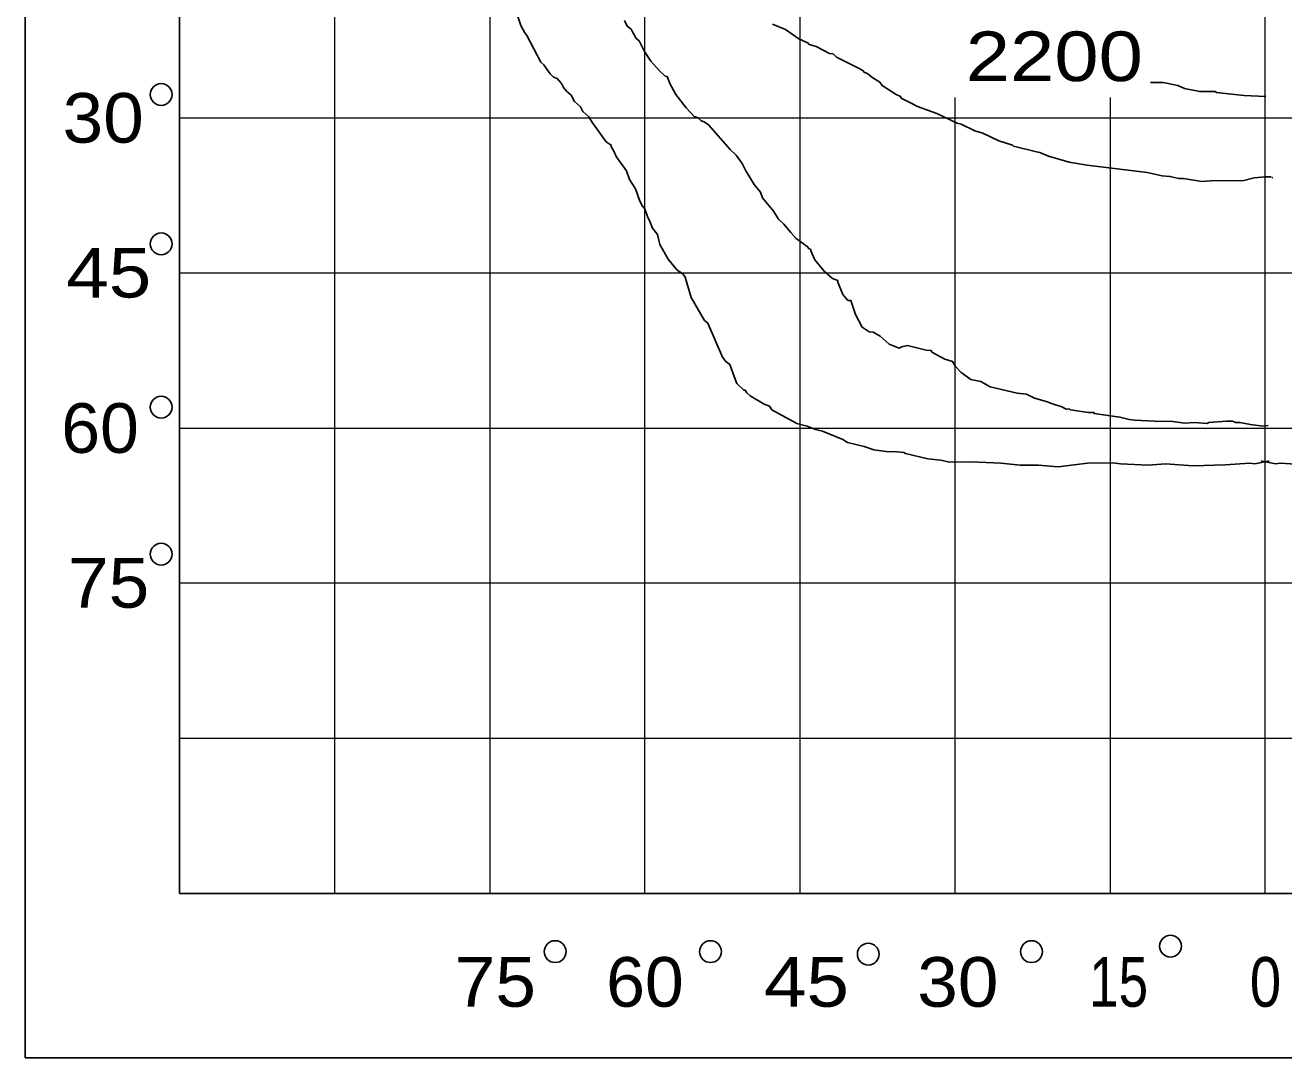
# Model space of a CAD drawing. Extents: x -39.6 to 16.1, y -17.6 to 34.
# Drawn here: x 8.955 to 11.491, y 19.458 to 21.539 of the extents above; entities that cross this region are included whole.
import ezdxf
from ezdxf.enums import TextEntityAlignment as Align

# ---------------------------------------------------------------- set-up
doc = ezdxf.new("R2010")
doc.units = 0
doc.header["$LTSCALE"] = 0.05
doc.layers.add('1', color=7, linetype='Continuous', lineweight=13)

msp = doc.modelspace()

# ---------------------------------------------------------------- linework, layer by layer
at = {"layer": '1', "lineweight": 25}
for p, q in [((8.95479, 19.45842), (8.95479, 24.24542)), ((9.26579, 19.78942), (9.26579, 23.85242)), ((11.46879, 21.23242), (11.46679, 21.23142)), ((9.26579, 19.78942), (13.95379, 19.78942)), ((8.95479, 19.45842), (13.95379, 19.45842))]:
    msp.add_line(p, q, dxfattribs=at)
at = {"layer": '1'}
for p, q in [((9.57879, 19.78942), (9.57879, 23.85242)), ((9.89179, 19.78942), (9.89179, 23.85242)), ((10.20379, 19.78942), (10.20379, 23.85242)), ((10.51679, 19.78942), (10.51679, 23.85242)), ((11.45379, 19.78942), (11.45379, 23.85242)), ((10.82879, 19.78942), (10.82879, 21.39342)), ((11.14179, 19.78942), (11.14179, 21.39342)), ((9.26579, 21.35242), (13.40679, 21.35242)), ((9.26579, 21.04042), (13.41179, 21.04042)), ((9.26579, 20.72742), (13.42279, 20.72742)), ((9.26579, 20.41542), (13.95379, 20.41542)), ((9.26579, 20.10242), (13.95379, 20.10242))]:
    msp.add_line(p, q, dxfattribs=at)
at = {"layer": '1', "lineweight": 25}
for points in [[(9.94279, 21.57042), (9.95379, 21.53842), (9.96179, 21.52342), (9.96579, 21.51842), (9.99379, 21.46442), (9.99979, 21.45942), (10.01279, 21.44142), (10.01979, 21.43442), (10.02679, 21.43142), (10.03579, 21.42142), (10.03979, 21.41342), (10.04579, 21.40642), (10.05479, 21.39842), (10.06179, 21.38542), (10.07379, 21.37442), (10.07879, 21.36542), (10.09079, 21.35442), (10.09779, 21.34242), (10.12579, 21.30442), (10.13579, 21.29742), (10.13579, 21.29442), (10.14079, 21.28542), (10.14579, 21.27442), (10.16679, 21.24542), (10.17279, 21.22842), (10.18479, 21.20942), (10.19379, 21.18442), (10.19879, 21.17442), (10.20379, 21.16942), (10.20879, 21.15342), (10.21379, 21.14342), (10.21879, 21.13042), (10.22879, 21.11742), (10.23379, 21.09742), (10.25079, 21.06742), (10.26879, 21.04542), (10.27979, 21.03842), (10.28479, 21.03142), (10.29679, 20.99042), (10.32379, 20.94442), (10.33079, 20.93842), (10.35979, 20.87042), (10.36679, 20.86142), (10.37479, 20.85542), (10.38179, 20.83642), (10.38879, 20.81742), (10.40279, 20.80342), (10.40579, 20.80342), (10.40879, 20.79842), (10.41579, 20.79242), (10.44379, 20.77542), (10.45479, 20.77142), (10.45979, 20.76442), (10.50979, 20.73642), (10.53079, 20.73142), (10.54779, 20.72442), (10.56179, 20.72142), (10.60279, 20.70442), (10.61179, 20.69842), (10.64579, 20.69042), (10.66479, 20.68342), (10.69479, 20.67942), (10.70279, 20.68042), (10.71179, 20.67942), (10.72579, 20.67842), (10.72879, 20.67642), (10.77379, 20.66542), (10.79979, 20.66242), (10.81779, 20.65842), (10.86179, 20.65942), (10.92079, 20.65642), (10.95979, 20.65242), (10.99679, 20.65242), (11.03679, 20.64942), (11.09579, 20.65642), (11.14679, 20.65742), (11.16179, 20.65542), (11.21779, 20.65242), (11.25279, 20.65542)], [(10.16279, 21.54842), (10.16779, 21.53742), (10.17579, 21.53142), (10.17779, 21.52742), (10.17879, 21.52542), (10.18579, 21.51242), (10.19179, 21.50742), (10.20279, 21.48642), (10.21579, 21.46642), (10.23279, 21.44742), (10.24479, 21.43642), (10.24879, 21.43542), (10.25379, 21.42142), (10.26579, 21.39942), (10.28679, 21.37242), (10.30279, 21.35542), (10.31079, 21.35242), (10.31679, 21.34642), (10.32279, 21.34442), (10.33179, 21.33842), (10.37579, 21.28842), (10.38779, 21.27742), (10.39979, 21.26042), (10.40679, 21.24542), (10.42379, 21.21842), (10.43679, 21.20242), (10.44079, 21.19142), (10.46279, 21.16442), (10.47279, 21.14842), (10.48379, 21.13842), (10.49779, 21.12142), (10.50879, 21.10942), (10.53079, 21.09342), (10.53479, 21.08842), (10.53779, 21.08742), (10.53779, 21.08442), (10.54579, 21.06642), (10.56479, 21.04342), (10.58179, 21.02842), (10.59279, 21.02442), (10.59279, 21.02142), (10.60279, 20.99642), (10.61279, 20.98442), (10.61879, 20.98442), (10.62779, 20.95642), (10.64179, 20.93042), (10.65579, 20.92142), (10.66379, 20.92042), (10.67779, 20.91242)], [(10.46079, 21.54142), (10.48679, 21.53042), (10.51379, 21.51142), (10.52979, 21.50442), (10.53179, 21.50342), (10.53479, 21.50042), (10.54879, 21.49642), (10.57579, 21.48242), (10.58279, 21.48142), (10.58979, 21.47442), (10.63679, 21.45142), (10.64379, 21.44742), (10.64579, 21.44442), (10.65279, 21.44142), (10.66079, 21.43442), (10.67679, 21.42442), (10.68179, 21.41742), (10.70979, 21.39942), (10.71879, 21.39542), (10.71979, 21.39242), (10.74279, 21.38042), (10.75279, 21.37542), (10.79179, 21.36142), (10.83279, 21.34142), (10.84079, 21.33942), (10.86879, 21.32642), (10.88479, 21.32142), (10.91679, 21.30642), (10.94479, 21.29742), (10.94679, 21.29542), (10.99579, 21.28342), (10.99979, 21.28242), (11.01679, 21.27542), (11.05879, 21.26342), (11.09479, 21.25742), (11.21579, 21.24242), (11.24579, 21.23542), (11.26179, 21.23442), (11.27979, 21.23042), (11.28879, 21.23042), (11.32579, 21.22442), (11.35279, 21.22642), (11.40779, 21.22542), (11.43179, 21.23142), (11.45379, 21.23342), (11.46579, 21.23342)], [(11.22279, 21.42342), (11.24779, 21.42342), (11.27779, 21.41742), (11.29079, 21.41142), (11.29779, 21.41042), (11.32179, 21.40542), (11.35279, 21.40542), (11.35579, 21.40342), (11.41079, 21.39742), (11.45479, 21.39542)], [(10.67779, 20.91242), (10.69579, 20.89642), (10.71579, 20.88842), (10.71979, 20.89042), (10.72379, 20.89142), (10.73279, 20.89342), (10.77079, 20.88442), (10.78079, 20.88342), (10.78179, 20.88042), (10.80779, 20.86642), (10.82379, 20.86142), (10.82979, 20.85142), (10.84079, 20.83942), (10.86079, 20.82542), (10.88079, 20.82142), (10.89979, 20.81042), (10.95379, 20.79742), (10.97279, 20.79542), (10.98879, 20.78742), (11.01479, 20.78042), (11.02079, 20.77742), (11.04379, 20.77042), (11.05279, 20.76542), (11.05879, 20.76642), (11.06079, 20.76442), (11.09779, 20.75842), (11.10879, 20.75842), (11.10879, 20.75642), (11.16079, 20.74942), (11.17979, 20.74442), (11.19079, 20.74342), (11.23079, 20.74142), (11.26779, 20.74042), (11.29079, 20.73742), (11.31179, 20.73842), (11.33679, 20.73642), (11.33979, 20.73842), (11.37579, 20.74142), (11.38779, 20.74142), (11.39379, 20.73842), (11.40279, 20.73842), (11.42379, 20.73442), (11.44879, 20.73142), (11.45979, 20.73242)], [(11.25279, 20.65542), (11.30879, 20.65142), (11.37279, 20.65342), (11.42279, 20.65642), (11.43279, 20.65542), (11.45979, 20.66042), (11.46179, 20.66042)], [(11.65479, 20.65542), (11.59879, 20.65142), (11.53479, 20.65342), (11.48479, 20.65642), (11.47479, 20.65542), (11.44779, 20.66042), (11.44579, 20.66042)]]:
    msp.add_lwpolyline(points, dxfattribs=at)
for centre in [(9.22879, 21.39942), (9.22879, 21.09842), (9.22879, 20.76942), (9.22879, 20.47342), (10.02279, 19.67242), (10.33579, 19.67242), (10.65379, 19.66742), (10.98279, 19.67242), (11.26279, 19.68342)]:
    msp.add_circle(centre, 0.022, dxfattribs=at)

# ---------------------------------------------------------------- texts
at = {"layer": '1'}
for s, width, p in [('2200', 1.2, (11.02879, 21.42642)), ('75', 1.1, (9.90229, 19.56142)), ('60', 1.05, (10.20379, 19.56142)), ('45', 1.15, (10.52929, 19.56142)), ('30', 1.1, (10.83429, 19.56142)), ('15', 0.8, (11.15829, 19.56142)), ('0', 0.85, (11.45429, 19.56142))]:
    msp.add_text(s, height=0.1, dxfattribs=dict(at, width=width)).set_placement(p, align=Align.CENTER)
for s, width, p in [('30', 1.1, (9.19379, 21.30242)), ('45', 1.15, (9.20879, 20.99042)), ('60', 1.05, (9.18379, 20.67742)), ('75', 1.1, (9.20479, 20.36542))]:
    msp.add_text(s, height=0.1, dxfattribs=dict(at, width=width)).set_placement(p, align=Align.RIGHT)

doc.saveas('drawing.dxf')
